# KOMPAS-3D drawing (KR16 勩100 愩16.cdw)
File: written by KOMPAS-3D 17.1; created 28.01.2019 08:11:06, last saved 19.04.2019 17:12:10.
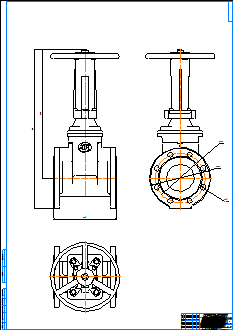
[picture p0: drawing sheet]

Sheet 1: A0, portrait

Title block, sheet 1: name: KR16 Ду100 Ру16; material: Внимание! Данный продукт является объектом авторского права ООО «Торговый Дом АДЛ». / Запрещается изменение, копирование, распространение / (в том числе путем копирования на другие сайты и ресурсы в Интернете) / или любое иное использование информации и объектов без предварительного / согласия правообладателя (ООО «Торговый Дом АДЛ»).; sheets: 1; organisation: ООО "Торговый дом АДЛ"; sheet format: A0; stored path: \\adlc.lan\data\АДЛ_ПКД\3D-модели\ADL production\Клиновые задвижки серии KR ГРАНАР\Клиновые задвижки KR16\Со штурвалом\KOMPAS 2D\KR16 Ду100.cdw

Views: Вид 1, Проекционный вид 2
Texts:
  user
Dimensions and other numbers on the sheet: 229; 462; 572; 180; 220; 19; 8 отв.; 1:1; 1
